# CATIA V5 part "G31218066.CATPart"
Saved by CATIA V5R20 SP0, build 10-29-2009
Part number: G31218066
Revision: 8
Definition: design
Nomenclature: G31218066
Source: made
Description: NOT SPECIFIED
Bounding box of the stored display mesh (mm): x -8 to 66, y -15.5 to 15.5, z -15.5 to 15.5
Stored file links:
  C:\Users\Raffaele\Desktop\3D X SITO CF\BOLEX\23-BUSH REF 312\G31218066.CATPart

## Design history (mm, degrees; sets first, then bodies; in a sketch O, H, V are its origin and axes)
Body1 "MANIFOLD_SOLID_BREP #17081" (main body)
  Solid1: solid without history
Body2 "MANIFOLD_SOLID_BREP #17228"
  Solid2: solid without history
Body3 "MANIFOLD_SOLID_BREP #17375"
  Solid3: solid without history
Body4 "MANIFOLD_SOLID_BREP #17522"
  Solid4: solid without history
Body5 "MANIFOLD_SOLID_BREP #17669"
  Solid5: solid without history
Body6 "MANIFOLD_SOLID_BREP #17818"
  Solid6: solid without history
Body7 "MANIFOLD_SOLID_BREP #17967"
  Solid7: solid without history
Body8 "MANIFOLD_SOLID_BREP #18116"
  Solid8: solid without history
Body9 "MANIFOLD_SOLID_BREP #18265"
  Solid9: solid without history
Body10 "MANIFOLD_SOLID_BREP #18414"
  Solid10: solid without history
Body11 "MANIFOLD_SOLID_BREP #18563"
  Solid11: solid without history
Body12 "MANIFOLD_SOLID_BREP #18712"
  Solid12: solid without history
Body13 "MANIFOLD_SOLID_BREP #18861"
  Solid13: solid without history
Body14 "MANIFOLD_SOLID_BREP #19010"
  Solid14: solid without history
Body15 "MANIFOLD_SOLID_BREP #19159"
  Solid15: solid without history
Body16 "MANIFOLD_SOLID_BREP #19308"
  Solid16: solid without history
Body17 "MANIFOLD_SOLID_BREP #19457"
  Solid17: solid without history
Body18 "MANIFOLD_SOLID_BREP #19606"
  Solid18: solid without history
Body19 "MANIFOLD_SOLID_BREP #19755"
  Solid19: solid without history
Body20 "MANIFOLD_SOLID_BREP #19904"
  Solid20: solid without history
Body21 "MANIFOLD_SOLID_BREP #20053"
  Solid21: solid without history
Body22 "MANIFOLD_SOLID_BREP #20202"
  Solid22: solid without history
Body23 "MANIFOLD_SOLID_BREP #20351"
  Solid23: solid without history
Body24 "MANIFOLD_SOLID_BREP #20500"
  Solid24: solid without history
Body25 "MANIFOLD_SOLID_BREP #20649"
  Solid25: solid without history
Body26 "MANIFOLD_SOLID_BREP #20798"
  Solid26: solid without history
Body27 "MANIFOLD_SOLID_BREP #20947"
  Solid27: solid without history
Body28 "MANIFOLD_SOLID_BREP #21096"
  Solid28: solid without history
Body29 "MANIFOLD_SOLID_BREP #21245"
  Solid29: solid without history
Body30 "MANIFOLD_SOLID_BREP #21394"
  Solid30: solid without history
Body31 "MANIFOLD_SOLID_BREP #21543"
  Solid31: solid without history
Body32 "MANIFOLD_SOLID_BREP #21690"
  Solid32: solid without history
Body33 "MANIFOLD_SOLID_BREP #21837"
  Solid33: solid without history
Body34 "MANIFOLD_SOLID_BREP #21986"
  Solid34: solid without history
Body35 "MANIFOLD_SOLID_BREP #22135"
  Solid35: solid without history
Body36 "MANIFOLD_SOLID_BREP #22284"
  Solid36: solid without history
Body37 "MANIFOLD_SOLID_BREP #22433"
  Solid37: solid without history
Body38 "MANIFOLD_SOLID_BREP #22582"
  Solid38: solid without history
Body39 "MANIFOLD_SOLID_BREP #22731"
  Solid39: solid without history
Body40 "MANIFOLD_SOLID_BREP #22880"
  Solid40: solid without history
Body41 "MANIFOLD_SOLID_BREP #23029"
  Solid41: solid without history
Body42 "MANIFOLD_SOLID_BREP #23178"
  Solid42: solid without history
Body43 "MANIFOLD_SOLID_BREP #23327"
  Solid43: solid without history
Body44 "MANIFOLD_SOLID_BREP #23476"
  Solid44: solid without history
Body45 "MANIFOLD_SOLID_BREP #23625"
  Solid45: solid without history
Body46 "MANIFOLD_SOLID_BREP #23774"
  Solid46: solid without history
Body47 "MANIFOLD_SOLID_BREP #23923"
  Solid47: solid without history
Body48 "MANIFOLD_SOLID_BREP #24072"
  Solid48: solid without history
Body49 "MANIFOLD_SOLID_BREP #24221"
  Solid49: solid without history
Body50 "MANIFOLD_SOLID_BREP #24370"
  Solid50: solid without history
Body51 "MANIFOLD_SOLID_BREP #24519"
  Solid51: solid without history
Body52 "MANIFOLD_SOLID_BREP #24668"
  Solid52: solid without history
Body53 "MANIFOLD_SOLID_BREP #24817"
  Solid53: solid without history
Body54 "MANIFOLD_SOLID_BREP #24966"
  Solid54: solid without history
Body55 "MANIFOLD_SOLID_BREP #25115"
  Solid55: solid without history
Body56 "MANIFOLD_SOLID_BREP #25262"
  Solid56: solid without history
Body57 "MANIFOLD_SOLID_BREP #25409"
  Solid57: solid without history
Body58 "MANIFOLD_SOLID_BREP #25558"
  Solid58: solid without history
Body59 "MANIFOLD_SOLID_BREP #25707"
  Solid59: solid without history
Body60 "MANIFOLD_SOLID_BREP #25856"
  Solid60: solid without history
Body61 "MANIFOLD_SOLID_BREP #26005"
  Solid61: solid without history
Body62 "MANIFOLD_SOLID_BREP #26154"
  Solid62: solid without history
Body63 "MANIFOLD_SOLID_BREP #26303"
  Solid63: solid without history
Body64 "MANIFOLD_SOLID_BREP #26450"
  Solid64: solid without history
Body65 "MANIFOLD_SOLID_BREP #26597"
  Solid65: solid without history
Body66 "MANIFOLD_SOLID_BREP #26746"
  Solid66: solid without history
Body67 "MANIFOLD_SOLID_BREP #26895"
  Solid67: solid without history
Body68 "MANIFOLD_SOLID_BREP #27044"
  Solid68: solid without history
Body69 "MANIFOLD_SOLID_BREP #27193"
  Solid69: solid without history
Body70 "MANIFOLD_SOLID_BREP #27342"
  Solid70: solid without history
Body71 "MANIFOLD_SOLID_BREP #27491"
  Solid71: solid without history
Body72 "MANIFOLD_SOLID_BREP #27640"
  Solid72: solid without history
Body73 "MANIFOLD_SOLID_BREP #27789"
  Solid73: solid without history
Body74 "MANIFOLD_SOLID_BREP #27938"
  Solid74: solid without history
Body75 "MANIFOLD_SOLID_BREP #28087"
  Solid75: solid without history
Body76 "MANIFOLD_SOLID_BREP #28236"
  Solid76: solid without history
Body77 "MANIFOLD_SOLID_BREP #28385"
  Solid77: solid without history
Body78 "MANIFOLD_SOLID_BREP #28534"
  Solid78: solid without history
Body79 "MANIFOLD_SOLID_BREP #28683"
  Solid79: solid without history
Body80 "MANIFOLD_SOLID_BREP #28832"
  Solid80: solid without history
Body81 "MANIFOLD_SOLID_BREP #28981"
  Solid81: solid without history
Body82 "MANIFOLD_SOLID_BREP #29130"
  Solid82: solid without history
Body83 "MANIFOLD_SOLID_BREP #29279"
  Solid83: solid without history
Body84 "MANIFOLD_SOLID_BREP #29428"
  Solid84: solid without history
Body85 "MANIFOLD_SOLID_BREP #29577"
  Solid85: solid without history
Body86 "MANIFOLD_SOLID_BREP #29724"
  Solid86: solid without history
Body87 "MANIFOLD_SOLID_BREP #29871"
  Solid87: solid without history
Body88 "MANIFOLD_SOLID_BREP #30018"
  Solid88: solid without history
Body89 "MANIFOLD_SOLID_BREP #30165"
  Solid89: solid without history
Body90 "MANIFOLD_SOLID_BREP #30314"
  Solid90: solid without history
Body91 "MANIFOLD_SOLID_BREP #30463"
  Solid91: solid without history
Body92 "MANIFOLD_SOLID_BREP #30612"
  Solid92: solid without history
Body93 "MANIFOLD_SOLID_BREP #30761"
  Solid93: solid without history
Body94 "MANIFOLD_SOLID_BREP #30910"
  Solid94: solid without history
Body95 "MANIFOLD_SOLID_BREP #31059"
  Solid95: solid without history
Body96 "MANIFOLD_SOLID_BREP #31208"
  Solid96: solid without history
Body97 "MANIFOLD_SOLID_BREP #31357"
  Solid97: solid without history
Body98 "MANIFOLD_SOLID_BREP #31506"
  Solid98: solid without history
Body99 "MANIFOLD_SOLID_BREP #31655"
  Solid99: solid without history
Body100 "MANIFOLD_SOLID_BREP #31804"
  Solid100: solid without history
Body101 "MANIFOLD_SOLID_BREP #31953"
  Solid101: solid without history
Body102 "MANIFOLD_SOLID_BREP #32102"
  Solid102: solid without history
Body103 "MANIFOLD_SOLID_BREP #32251"
  Solid103: solid without history
Body104 "MANIFOLD_SOLID_BREP #32400"
  Solid104: solid without history
Body105 "MANIFOLD_SOLID_BREP #32549"
  Solid105: solid without history
Body106 "MANIFOLD_SOLID_BREP #32698"
  Solid106: solid without history
Body107 "MANIFOLD_SOLID_BREP #32847"
  Solid107: solid without history
Body108 "MANIFOLD_SOLID_BREP #32996"
  Solid108: solid without history
Body109 "MANIFOLD_SOLID_BREP #33145"
  Solid109: solid without history
Body110 "MANIFOLD_SOLID_BREP #33294"
  Solid110: solid without history
Body111 "MANIFOLD_SOLID_BREP #33443"
  Solid111: solid without history
Body112 "MANIFOLD_SOLID_BREP #33590"
  Solid112: solid without history
Body113 "MANIFOLD_SOLID_BREP #33737"
  Solid113: solid without history
Body114 "MANIFOLD_SOLID_BREP #33886"
  Solid114: solid without history
Body115 "MANIFOLD_SOLID_BREP #34035"
  Solid115: solid without history
Body116 "MANIFOLD_SOLID_BREP #34184"
  Solid116: solid without history
Body117 "MANIFOLD_SOLID_BREP #34333"
  Solid117: solid without history
Body118 "MANIFOLD_SOLID_BREP #34482"
  Solid118: solid without history
Body119 "MANIFOLD_SOLID_BREP #34631"
  Solid119: solid without history
Body120 "MANIFOLD_SOLID_BREP #34780"
  Solid120: solid without history
Body121 "MANIFOLD_SOLID_BREP #34929"
  Solid121: solid without history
